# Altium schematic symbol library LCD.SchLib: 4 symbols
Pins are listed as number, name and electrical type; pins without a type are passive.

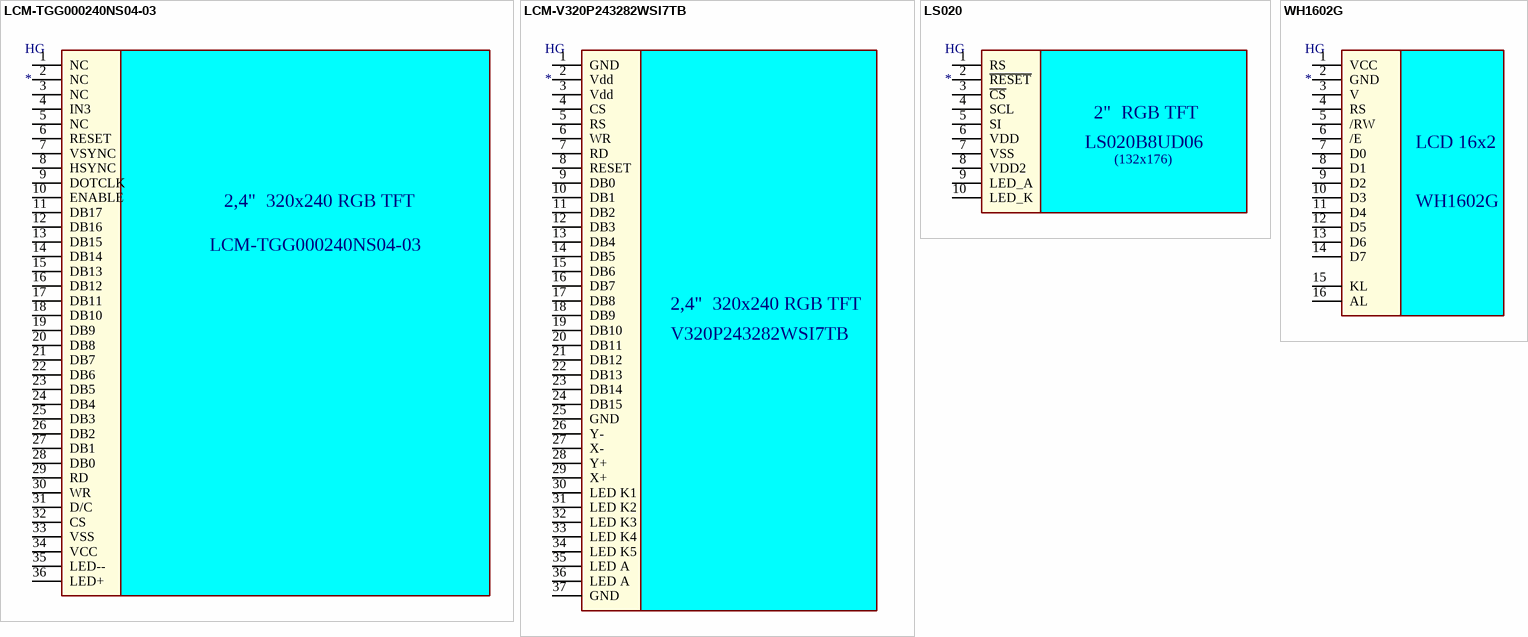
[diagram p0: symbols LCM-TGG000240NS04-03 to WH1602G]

## LCM-TGG000240NS04-03
designator HG
TFT RGB 2,4" 320x240
footprint LCM-TGG000240NS04-03
pins: 1 NC, 2 NC, 3 NC, 4 IN3, 5 NC, 6 RESET, 7 VSYNC, 8 HSYNC, 9 DOTCLK, 10 ENABLE, 11 DB17, 12 DB16, 13 DB15, 14 DB14, 15 DB13, 16 DB12, 17 DB11, 18 DB10, 19 DB9, 20 DB8, 21 DB7, 22 DB6, 23 DB5, 24 DB4, 25 DB3, 26 DB2, 27 DB1, 28 DB0, 29 RD, 30 WR, 31 D/C, 32 CS, 33 VSS, 34 VCC, 35 LED--, 36 LED+

## LCM-V320P243282WSI7TB
designator HG
TFT RGB 2,4" 320x240
footprint LCM-V320P243282WSI7TB
pins: 1 GND, 2 Vdd, 3 Vdd, 4 CS, 5 RS, 6 WR, 7 RD, 8 RESET, 9 DB0, 10 DB1, 11 DB2, 12 DB3, 13 DB4, 14 DB5, 15 DB6, 16 DB7, 17 DB8, 18 DB9, 19 DB10, 20 DB11, 21 DB12, 22 DB13, 23 DB14, 24 DB15, 25 GND, 26 Y-, 27 X-, 28 Y+, 29 X+, 30 LED K1, 31 LED K2, 32 LED K3, 33 LED K4, 34 LED K5, 35 LED A, 36 LED A, 37 GND

## LS020
designator HG
TFT RGB 2" 132x176
footprint LS020
pins: 1 RS, 2 ~{RESET}, 3 ~{CS}, 4 SCL, 5 SI, 6 VDD, 7 VSS, 8 VDD2, 9 LED_A, 10 LED_K

## WH1602G
designator HG
LCD 16x2
footprint WH1602G
pins: 1 VCC, 2 GND, 3 V, 4 RS, 5 /RW, 6 /E, 7 D0, 8 D1, 9 D2, 10 D3, 11 D4, 12 D5, 13 D6, 14 D7, 15 KL, 16 AL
